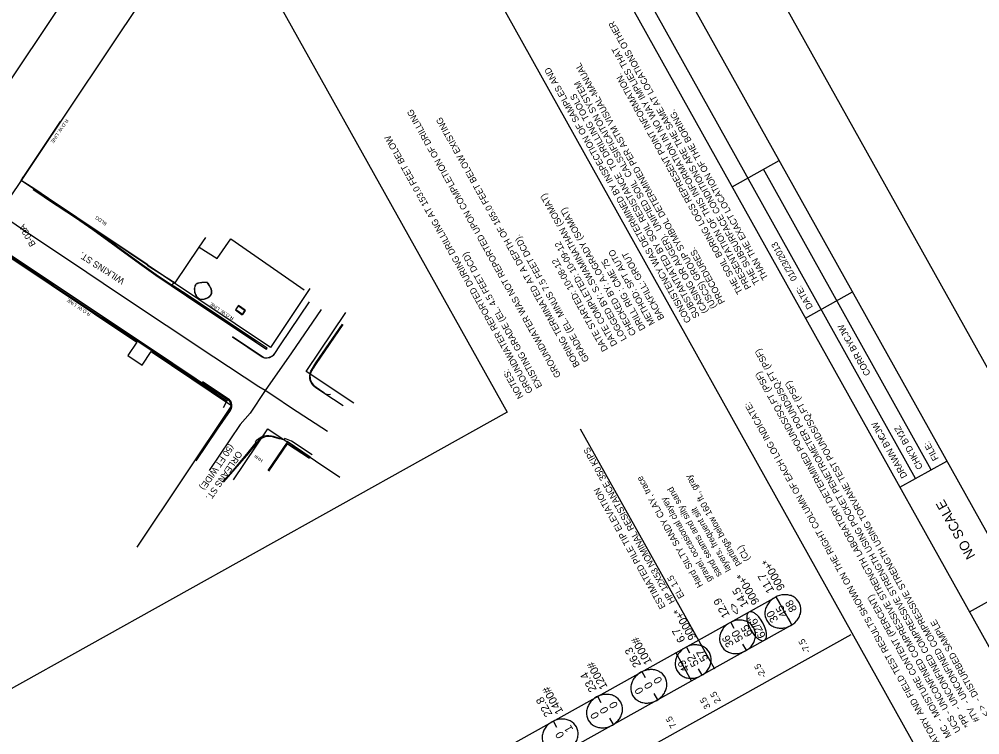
# Model space of a CAD drawing. Extents: x 13482447 to 13495412, y 324533 to 340229.
# Drawn here: x 13494341 to 13495055, y 332109 to 332641 of the extents above; entities that cross this region are included whole.
import ezdxf

# ---------------------------------------------------------------- set-up
doc = ezdxf.new("R2010")
doc.units = 0
for name, color, linetype in [('BORDER', 7, 'Continuous'), ('Default', 7, 'Continuous'), ('DETAIL_TEXT_DIMEN_PR', 7, 'Continuous'), ('Level 1', 7, 'Continuous'), ('TYPICAL_TEXT_DIMEN_PR', 7, 'Continuous'), ('V-ANNO-TEXT', 7, 'Continuous'), ('V-BLDG-IDEN', 7, 'Continuous'), ('V-BLDG-OTLN', 7, 'Continuous'), ('V-PROP-RWAY', 7, 'Continuous'), ('V-PROP-RWAY-IDEN', 7, 'Continuous'), ('V-PVMT-BACK', 7, 'Continuous'), ('V-PVMT-CNTR', 7, 'Continuous'), ('V-PVMT-ROAD', 7, 'Continuous'), ('V-SITE-FENC-DEMO', 7, 'Continuous'), ('V-STRC-WALL', 7, 'Continuous'), ('V-TOPO-IDEN', 7, 'Continuous')]:
    doc.layers.add(name, color=color, linetype=linetype)

# ---------------------------------------------------------------- blocks, each defined once
blk = doc.blocks.new('DGRFC_BLOW$COUNT$ELLIPSE')
at = {"layer": 'Default'}
blk.add_lwpolyline([(0, -0.0274), (0.0061, -0.0265), (0.0089, -0.0254), (0.0104, -0.0246), (0.0118, -0.0238), (0.0132, -0.0228), (0.0145, -0.0218), (0.0157, -0.0206), (0.0168, -0.0194), (0.0179, -0.018), (0.0189, -0.0167), (0.0198, -0.0152), (0.0206, -0.0137), (0.0213, -0.0122), (0.022, -0.0106), (0.023, -0.0071), (0.0236, -0.0036), (0.0238, 0), (0.0236, 0.0036), (0.023, 0.0071), (0.022, 0.0106), (0.0213, 0.0122), (0.0206, 0.0137), (0.0198, 0.0152), (0.0189, 0.0167), (0.0179, 0.018), (0.0168, 0.0194), (0.0157, 0.0206), (0.0145, 0.0218), (0.0132, 0.0228), (0.0118, 0.0238), (0.0104, 0.0246), (0.0089, 0.0254), (0.0061, 0.0265), (0, 0.0274), (-0.0061, 0.0265), (-0.0089, 0.0254), (-0.0104, 0.0246), (-0.0118, 0.0238), (-0.0132, 0.0228), (-0.0145, 0.0218), (-0.0157, 0.0206), (-0.0168, 0.0194), (-0.0179, 0.018), (-0.0189, 0.0167), (-0.0198, 0.0152), (-0.0206, 0.0137), (-0.0213, 0.0122), (-0.022, 0.0106), (-0.023, 0.0071), (-0.0236, 0.0036), (-0.0238, 0), (-0.0236, -0.0036), (-0.023, -0.0071), (-0.022, -0.0106), (-0.0213, -0.0122), (-0.0206, -0.0137), (-0.0198, -0.0152), (-0.0189, -0.0167), (-0.0179, -0.018), (-0.0168, -0.0194), (-0.0157, -0.0206), (-0.0145, -0.0218), (-0.0132, -0.0228), (-0.0118, -0.0238), (-0.0104, -0.0246), (-0.0089, -0.0254), (-0.0061, -0.0265), (0, -0.0274)], dxfattribs=at)

msp = doc.modelspace()

# ---------------------------------------------------------------- linework, layer by layer
at = {"layer": 'Default'}
for points in [[(13494457.44, 332789.11), (13494703.36, 332348.37)], [(13494703.36, 332348.37), (13494205.48, 332070.8)], [(13494374.94, 331916.13), (13494903.54, 332211.14)], [(13494915.18, 332190.27), (13494903.49, 332211.23)], [(13494386.58, 331895.26), (13494915.18, 332190.27)], [(13494959.11, 332182.88), (13494336.71, 331835.6)], [(13494840.6, 332148.67), (13494828.91, 332169.62)]]:
    msp.add_lwpolyline(points, dxfattribs=at)
at = {"layer": 'Level 1'}
for p, q in [((13495412.28, 331751.04), (13494712.57, 333005.04)), ((13495330.65, 331774.2), (13494689.41, 332923.41)), ((13495295.72, 331754.71), (13494654.48, 332903.92)), ((13495223.39, 331712.33), (13494580.84, 332863.9)), ((13495007.21, 332299.13), (13494695.36, 332858.02)), ((13494870.84, 332516.2), (13494905.78, 332535.69)), ((13495018.85, 332305.63), (13494894.11, 332529.18)), ((13494925.4, 332418.38), (13494960.33, 332437.87)), ((13494995.56, 332292.64), (13495030.5, 332312.13)), ((13495047.21, 332200.07), (13495082.14, 332219.56))]:
    msp.add_line(p, q, dxfattribs=at)
at = {"layer": 'TYPICAL_TEXT_DIMEN_PR'}
for p, q in [((13494857.81, 332157.23), (13494758.09, 332335.95)), ((13494906.13, 332206.49), (13494903.54, 332211.14)), ((13494872.38, 332187.6), (13494869.78, 332192.24)), ((13494915.18, 332190.27), (13494912.59, 332194.92)), ((13494839.39, 332169.19), (13494836.8, 332173.84)), ((13494881.43, 332171.38), (13494878.84, 332176.02)), ((13494806.4, 332150.78), (13494803.81, 332155.43)), ((13494848.44, 332152.97), (13494845.85, 332157.61)), ((13494815.45, 332134.56), (13494812.86, 332139.21)), ((13494773.41, 332132.38), (13494770.82, 332137.02)), ((13494740.42, 332113.97), (13494737.83, 332118.61)), ((13494782.46, 332116.15), (13494779.87, 332120.8))]:
    msp.add_line(p, q, dxfattribs=at)
at = {"layer": 'V-BLDG-OTLN'}
for points in [[(13494343.43, 332523.28), (13494342, 332521.11), (13494351.5, 332514.97), (13494362.36, 332507.58), (13494383.44, 332493.51), (13494396.16, 332484.98), (13494436.22, 332458.43), (13494435.76, 332457.89), (13494456.71, 332444.65), (13494474.49, 332471.19), (13494479.39, 332478.39)], [(13494556.95, 332314.92), (13494539.87, 332326.2), (13494525.55, 332304.99)], [(13494526.15, 332304.58), (13494540.09, 332324.93), (13494556.46, 332314.19)]]:
    msp.add_lwpolyline(points, dxfattribs=at)
at = {"layer": 'V-PROP-RWAY'}
for p, q in [((13494162.94, 332339.78), (13494415.51, 332716.95)), ((13494441.77, 332669.89), (13494189.2, 332292.72)), ((13494341.99, 332520.8), (13494371.36, 332564.67)), ((13494527.47, 332396.63), (13494341.99, 332520.8)), ((13494333.01, 332464.24), (13494428.07, 332400.6)), ((13494556.84, 332440.51), (13494527.47, 332396.63)), ((13494554.06, 332378.83), (13494583.43, 332422.71)), ((13494428.07, 332400.6), (13494421.4, 332390.63)), ((13494421.4, 332390.63), (13494432.03, 332383.51)), ((13494432.03, 332383.51), (13494438.71, 332393.48)), ((13494438.71, 332393.48), (13494498.54, 332353.42)), ((13494589.54, 332355.08), (13494554.06, 332378.83)), ((13494498.54, 332353.42), (13494428.05, 332248.13)), ((13494500.08, 332298.2), (13494525.4, 332336.02)), ((13494525.4, 332336.02), (13494578.99, 332300.15))]:
    msp.add_line(p, q, dxfattribs=at)
at = {"layer": 'V-PVMT-BACK'}
for points in [[(13494581.22, 332413.73), (13494561.51, 332384.74), (13494559.24, 332381.12), (13494558.02, 332379), (13494557.55, 332377.99), (13494557.06, 332376.48), (13494556.86, 332374.95), (13494556.88, 332374.17), (13494557.05, 332373.11), (13494557.25, 332372.4), (13494557.8, 332371.05), (13494558.08, 332370.52), (13494558.75, 332369.53), (13494559.54, 332368.63), (13494560.13, 332368.07), (13494561.49, 332367.02), (13494567.19, 332363.04), (13494567.06, 332362.79)], [(13494472.22, 332312.25), (13494487.68, 332336.18), (13494491.11, 332341.45), (13494496.52, 332348.72), (13494497.47, 332350.12), (13494498.04, 332351.33), (13494498.31, 332352.64), (13494498.27, 332353.98), (13494497.9, 332355.27), (13494497.25, 332356.44), (13494496.34, 332357.41), (13494495.77, 332357.83)], [(13494492.65, 332351.94), (13494494.95, 332356.59), (13494495.77, 332357.83)], [(13494534.6, 332328.53), (13494533.98, 332328.69), (13494529.82, 332329.93), (13494529.1, 332330.12), (13494527.22, 332330.42), (13494525.32, 332330.39), (13494523.45, 332330.05), (13494521.67, 332329.4), (13494520.02, 332328.46), (13494518.55, 332327.25), (13494517.3, 332325.82), (13494517.24, 332325.73), (13494511.17, 332318.01), (13494492.55, 332296.67)]]:
    msp.add_lwpolyline(points, dxfattribs=at)
at = {"layer": 'V-PVMT-CNTR'}
for points in [[(13494569.9, 332334.19), (13494543.09, 332351.45), (13494530, 332360.31), (13494523.55, 332364.49), (13494518.82, 332367.3), (13494485.34, 332389.34), (13494450.03, 332412.95), (13494414.45, 332436.54), (13494379.49, 332460.03), (13494345.6, 332482.5), (13494327.31, 332495.27), (13494298.14, 332514.29), (13494271.57, 332532.13), (13494238.98, 332554.15), (13494204.65, 332577.08), (13494171.55, 332599.53), (13494143.69, 332618.17)], [(13494565.21, 332424.85), (13494543.23, 332392.53), (13494523.55, 332364.49), (13494512.34, 332347.83), (13494505.02, 332339.39), (13494481.96, 332305.2)]]:
    msp.add_lwpolyline(points, dxfattribs=at)
at = {"layer": 'V-PVMT-ROAD'}
for points in [[(13494383.26, 332493.54), (13494382.64, 332493.41), (13494362.55, 332506.72), (13494362.46, 332507.55)], [(13494474.49, 332471.19), (13494487.87, 332462.68), (13494497.88, 332477.35), (13494527.28, 332457.02), (13494552.61, 332439.58)], [(13494480.72, 332444.84), (13494477.81, 332444.91), (13494476.54, 332444.88), (13494474.88, 332444.71), (13494473.49, 332444.36), (13494472.9, 332444.11), (13494472.24, 332443.68), (13494471.95, 332443.42), (13494471.58, 332442.97), (13494471.16, 332442.16), (13494470.86, 332440.82), (13494470.82, 332440.16), (13494470.89, 332438.75), (13494471.09, 332437.67), (13494471.6, 332436.08), (13494471.95, 332435.34), (13494472.52, 332434.43), (13494472.85, 332434.02), (13494473.39, 332433.48), (13494474.32, 332432.86), (13494475.31, 332432.51), (13494476.02, 332432.4), (13494477.5, 332432.44), (13494478.25, 332432.58), (13494479.73, 332433.05), (13494480.66, 332433.5), (13494481.78, 332434.21), (13494482.27, 332434.61), (13494483.15, 332435.58), (13494483.59, 332436.35), (13494483.77, 332436.88), (13494483.89, 332438.01), (13494483.83, 332438.61), (13494483.51, 332439.89), (13494482.93, 332441.29), (13494482.42, 332442.3), (13494481.12, 332444.54)], [(13494480.58, 332444.78), (13494477.75, 332444.82), (13494476.51, 332444.77), (13494474.89, 332444.6), (13494473.54, 332444.25), (13494472.97, 332444), (13494472.32, 332443.58), (13494472.04, 332443.33), (13494471.68, 332442.89), (13494471.28, 332442.1), (13494470.99, 332440.76), (13494470.95, 332440.09), (13494471.05, 332438.68), (13494471.26, 332437.59), (13494471.8, 332436.01), (13494472.17, 332435.27), (13494472.75, 332434.37), (13494473.09, 332433.97), (13494473.64, 332433.44), (13494474.58, 332432.85), (13494475.54, 332432.54), (13494476.22, 332432.46), (13494477.64, 332432.54), (13494478.36, 332432.69), (13494479.77, 332433.18), (13494480.65, 332433.62), (13494481.72, 332434.33), (13494482.18, 332434.73), (13494483.03, 332435.67), (13494483.46, 332436.46), (13494483.64, 332437), (13494483.74, 332438.15), (13494483.66, 332438.76), (13494483.3, 332440.05), (13494482.65, 332441.46), (13494482.08, 332442.48), (13494480.65, 332444.73)], [(13494556.28, 332430.52), (13494534.75, 332398.59), (13494530.07, 332391.41), (13494529.47, 332390.66), (13494529.02, 332390.24), (13494527.99, 332389.55), (13494526.72, 332388.98), (13494526.05, 332388.77), (13494525.02, 332388.59), (13494523.93, 332388.57), (13494523.39, 332388.64), (13494522.58, 332388.85), (13494521.41, 332389.44), (13494499.21, 332404.28)], [(13494508.68, 332424.44), (13494503.76, 332427.86), (13494501.51, 332424.52), (13494506.52, 332420.94), (13494508.68, 332424.44)], [(13494506.67, 332421.21), (13494501.76, 332424.6), (13494503.75, 332427.6), (13494508.73, 332424.22), (13494506.67, 332421.21)], [(13494581.44, 332353.13), (13494567.08, 332362.54), (13494561.17, 332366.67), (13494559.77, 332367.73), (13494558.59, 332369.03), (13494557.66, 332370.52), (13494557.01, 332372.15), (13494556.67, 332373.88), (13494556.65, 332375.63), (13494556.94, 332377.36), (13494557.55, 332379.01), (13494557.88, 332379.66), (13494561.17, 332385.16), (13494580.94, 332413.83)], [(13494529.95, 332391.58), (13494529.12, 332390.63), (13494528.66, 332390.22), (13494527.9, 332389.71), (13494526.94, 332389.27), (13494526.44, 332389.09), (13494525.71, 332388.89), (13494524.82, 332388.72), (13494524.47, 332388.7), (13494523.75, 332388.72), (13494522.76, 332388.94), (13494522.25, 332389.13), (13494521.5, 332389.55), (13494499.3, 332404.4)], [(13494472.3, 332312.21), (13494488.13, 332335.88), (13494497.78, 332349.83), (13494498.41, 332351.09), (13494498.75, 332352.46), (13494498.78, 332353.88), (13494498.48, 332355.26), (13494497.89, 332356.54), (13494497.02, 332357.65), (13494496, 332358.49), (13494477.01, 332371.04)], [(13494495.44, 332358.14), (13494476.75, 332370.64)], [(13494495.44, 332358.14), (13494495.28, 332358.46), (13494476.92, 332370.9)], [(13494567.06, 332362.79), (13494568.35, 332362.13), (13494569.75, 332361.78), (13494571.2, 332361.73), (13494572.19, 332361.89)], [(13494492.1, 332296.91), (13494499.81, 332305.04), (13494510.87, 332318.46), (13494516.88, 332326.01), (13494516.31, 332326.42), (13494517.57, 332327.89), (13494519.05, 332329.12), (13494520.72, 332330.1), (13494522.53, 332330.78), (13494524.42, 332331.16), (13494526.35, 332331.22), (13494528.27, 332330.97), (13494529.56, 332330.61), (13494534.73, 332328.98)], [(13494558.52, 332316.63), (13494543.11, 332327.03), (13494538.17, 332328.88), (13494537.37, 332327.87), (13494534.6, 332328.53)], [(13494557, 332315.02), (13494539.78, 332326.54)]]:
    msp.add_lwpolyline(points, dxfattribs=at)
at = {"layer": 'V-SITE-FENC-DEMO'}
msp.add_lwpolyline([(13494516.88, 332400.98), (13494454.22, 332442.65), (13494455.75, 332444.95)], dxfattribs=at)
at = {"layer": 'V-STRC-WALL'}
for points in [[(13494351.43, 332514.71), (13494351.07, 332514.18), (13494355.23, 332511.27), (13494362.38, 332506.51), (13494382.49, 332493.21), (13494395.33, 332484.24), (13494430.14, 332459.16), (13494442.14, 332450.44), (13494465.06, 332435.12), (13494500.32, 332411.42), (13494524.53, 332395.31), (13494524.9, 332396.06), (13494465.42, 332435.8), (13494455.18, 332442.46)], [(13494351.43, 332514.71), (13494355.67, 332511.89), (13494362.4, 332507.39), (13494362.49, 332506.66), (13494382.59, 332493.35), (13494383.18, 332493.48), (13494395.72, 332484.73), (13494430.44, 332459.61), (13494442.51, 332450.97), (13494455.18, 332442.46)], [(13494494.85, 332356.7), (13494495.33, 332357.66), (13494472.3, 332373.02), (13494438.14, 332395.84), (13494402.73, 332419.43), (13494366.86, 332443.47), (13494332.26, 332466.53), (13494315.83, 332477.56), (13494315.57, 332477.73)], [(13494494.85, 332356.7), (13494471.69, 332372.25), (13494437.65, 332394.97), (13494402.11, 332418.69), (13494366.37, 332442.49), (13494331.57, 332465.72), (13494317.33, 332475.26)]]:
    msp.add_lwpolyline(points, dxfattribs=at)

# ---------------------------------------------------------------- block references
at = {"layer": 'Default'}
for p, xscale, yscale, rotation in [((13494908.57, 332200.26), 503.9370078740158, 503.93700787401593, 119.16052892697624), ((13494908.57, 332200.26), 503.9370078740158, 503.93700787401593, 119.16052892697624), ((13494888.99, 332189.28), 503.9370078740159, 189.3040511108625, 119.16052892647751), ((13494874.82, 332181.37), 503.9370078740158, 503.93700787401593, 119.16052892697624), ((13494874.82, 332181.37), 503.9370078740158, 503.93700787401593, 119.16052892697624), ((13494841.83, 332162.96), 503.9370078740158, 503.93700787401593, 119.16052892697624), ((13494841.83, 332162.96), 503.9370078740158, 503.93700787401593, 119.16052892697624), ((13494808.84, 332144.56), 503.9370078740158, 503.93700787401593, 119.16052892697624), ((13494808.84, 332144.56), 503.9370078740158, 503.93700787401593, 119.16052892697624), ((13494775.85, 332126.15), 503.9370078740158, 503.93700787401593, 119.16052892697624), ((13494775.85, 332126.15), 503.9370078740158, 503.93700787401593, 119.16052892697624), ((13494742.86, 332107.74), 503.9370078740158, 503.93700787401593, 119.16052892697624), ((13494742.86, 332107.74), 503.9370078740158, 503.93700787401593, 119.16052892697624)]:
    msp.add_blockref('DGRFC_BLOW$COUNT$ELLIPSE', p, dxfattribs=dict(at, xscale=xscale, yscale=yscale, rotation=rotation))

# ---------------------------------------------------------------- texts
at = {"layer": 'BORDER'}
for s, p in [('THE SUBSURFACE CONDITIONS ARE THE SAME AT LOCATIONS OTHER ', (13494891.49, 332444.89)), ('PRESENTATION OF THIS INFORMATION IN NO WAY IMPLIES THAT ', (13494885.2, 332441.38)), ('CONSISTENCY WAS DETERMINED BY INSPECTION OF SAMPLES AND ', (13494840.51, 332416.44)), ('(USCS) GROUP SYMBOL DETERMINED PER ASTM VISUAL-MANUAL ', (13494859.37, 332426.97)), ('THE SOIL BORING LOGS REPRESENT POINT INFORMATION. ', (13494878.91, 332437.88)), ('(CASING OR AUGER).  UNIFIED SOIL  CALSSIFICAITON SYSTEM ', (13494853.08, 332423.46)), ('SUBSTANTIATED BY SOIL RESISTANCE  TO DRILLING TOOLS ', (13494846.79, 332419.95)), ('THAN THE EXACT LOCATION OF THE BORING.', (13494897.78, 332448.4)), ('PROCEDURES.', (13494865.66, 332430.48)), ('*PP  - UNCONFINED COMPRESSIVE STRENGTH USING POCKET PENETROMETER POUNDS/SQ.FT (PSF)', (13495048.01, 332115.56)), ('UCS - UNCONFINED COMPRESSIVE STRENGTH LABORATORY DETERMINED POUNDS/SQ.FT (PSF)', (13495041.03, 332111.67)), ('#TV  - UNCONFINED COMPRESSIVE STRENGTH USING TORVANE TEST POUNDS/SQ.FT (PSF)', (13495055, 332119.46)), ('LABORATORY AND FIELD TEST RESULTS SHOWN ON THE RIGHT COLUMN OF EACH LOG INDICATE:', (13495035.63, 332084.53)), ('MC  - MOISTURE CONTENT (PERCENT)', (13495034.04, 332107.77)), ('< >  - DISTURBED SAMPLE   ', (13495061.98, 332123.36))]:
    msp.add_text(s, height=4.8, rotation=119.16053, dxfattribs=at).set_placement(p)
at = {"layer": 'Default'}
for s, height, p in [('9000+*', 5.952, (13494910.31, 332217.83)), ('9000+*', 5.952, (13494891.29, 332207.22)), (' 11.7', 5.952, (13494903.32, 332213.93)), (' 11.7', 5.952, (13494903.32, 332213.93)), (' 14.5', 5.952, (13494884.3, 332203.32)), (' 14.5', 5.952, (13494884.3, 332203.32)), (' 12.9', 5.952, (13494870.33, 332195.52)), (' 12.9', 5.952, (13494870.33, 332195.52)), ('<>', 5.952, (13494877.32, 332199.42)), ('<>', 5.952, (13494877.32, 332199.42)), ('45', 5.952, (13494912.28, 332197.88)), ('45', 5.952, (13494912.28, 332197.88)), ('88', 5.952, (13494919.26, 332201.77)), ('88', 5.952, (13494919.26, 332201.77)), ('9000+*', 5.952, (13494844.33, 332181.01)), ('62/6"', 5.952, (13494896.09, 332182.19)), ('30', 5.952, (13494905.29, 332193.98)), ('30', 5.952, (13494905.29, 332193.98)), ('65', 5.952, (13494886.27, 332183.37)), ('65', 5.952, (13494886.27, 332183.37)), ('1000#', 5.952, (13494811.34, 332162.61)), ('1000#', 5.952, (13494811.34, 332162.61)), (' 6.7', 5.952, (13494837.34, 332177.11)), (' 6.7', 5.952, (13494837.34, 332177.11)), ('36', 5.952, (13494872.3, 332175.57)), ('36', 5.952, (13494872.3, 332175.57)), ('50', 5.952, (13494879.29, 332179.47)), ('50', 5.952, (13494879.29, 332179.47)), (' 26.3', 5.952, (13494804.35, 332158.71)), (' 26.3', 5.952, (13494804.35, 332158.71)), ('52', 5.952, (13494846.3, 332161.06)), ('52', 5.952, (13494846.3, 332161.06)), ('57', 5.952, (13494853.28, 332164.96)), ('57', 5.952, (13494853.28, 332164.96)), ('1200#', 5.952, (13494778.35, 332144.2)), ('1200#', 5.952, (13494778.35, 332144.2)), ('49', 5.952, (13494839.31, 332157.16)), ('49', 5.952, (13494839.31, 332157.16)), (' 23.4', 5.952, (13494771.36, 332140.3)), (' 23.4', 5.952, (13494771.36, 332140.3)), ('0', 5.95, (13494812.18, 332144.68)), ('0', 5.95, (13494812.18, 332144.68)), ('0', 5.95, (13494819.16, 332148.58)), ('0', 5.95, (13494819.16, 332148.58)), ('1400#', 5.952, (13494745.36, 332125.79)), ('1400#', 5.952, (13494745.36, 332125.79)), ('0', 5.95, (13494805.19, 332140.78)), ('0', 5.95, (13494805.19, 332140.78)), (' 22.8', 5.952, (13494738.37, 332121.89)), (' 22.8', 5.952, (13494738.37, 332121.89)), ('0', 5.95, (13494786.17, 332130.17)), ('0', 5.95, (13494786.17, 332130.17)), ('0', 5.95, (13494772.2, 332122.38)), ('0', 5.95, (13494772.2, 332122.38)), ('0', 5.95, (13494779.19, 332126.27)), ('0', 5.95, (13494779.19, 332126.27)), ('0', 5.95, (13494746.2, 332107.87)), ('0', 5.95, (13494746.2, 332107.87)), ('1', 5.95, (13494752.8, 332112.45)), ('1', 5.95, (13494752.8, 332112.45))]:
    msp.add_text(s, height=height, rotation=119.16053, dxfattribs=at).set_placement(p)
at = {"layer": 'DETAIL_TEXT_DIMEN_PR'}
for s, p in [('GROUNDWATER WAS NOT REPORTED UPON COMPLETION OF DRILLING ', (13494743.7, 332375.67)), ('BORING TERMINATED AT A DEPTH OF 165.0 FEET BELOW EXISTING ', (13494757.67, 332383.46)), ('GROUNDWATER REPORTED DURING DRILLING AT 153.0 FEET BELOW', (13494722.74, 332363.97)), ('LOGGED BY: S.SWAMINATHAN (SOMAT)', (13494792.61, 332402.95)), ('CHECKED BY: A.OGRADY (SOMAT)', (13494799.59, 332406.85)), ('B-03A', (13494353.06, 332473.25)), ('GRADE (EL. MINUS 7.5 FEET DCD).', (13494764.66, 332387.36)), ('DATE COMPLETED: 10-09-12', (13494785.62, 332399.05)), ('EXISTING GRADE (EL. 4.5 FEET DCD)', (13494729.73, 332367.87)), ('METHOD: SPT AUTO', (13494813.56, 332414.65)), ('BACKFILL: GROUT', (13494820.55, 332418.54)), ('DATE STARTED: 10-08-12', (13494778.63, 332395.16)), ('DRILL RIG : CME 75', (13494806.58, 332410.75)), ('NOTES:', (13494715.76, 332360.07)), ('HP 12X53 NOMINAL RESISTANCE 350 KIPS', (13494828.45, 332207.61)), ('Hard SILTY SANDY CLAY, trace ', (13494849.3, 332219.58)), ('partings below 160 ft., gray ', (13494877.24, 332235.17)), ('ESTIMATED PILE TIP ELEVATION', (13494821.47, 332203.72)), ('sand seams and silty sand ', (13494863.27, 332227.38)), ('gravel, occasional clayey ', (13494856.28, 332223.48)), ('layers, frequent silt ', (13494870.26, 332231.28)), ('(CL)', (13494884.23, 332239.07)), ('EL 1.5', (13494835.44, 332211.51)), ('-7.5', (13494929.38, 332170.76)), ('-2.5', (13494896.39, 332152.36)), ('2.5', (13494862.63, 332133.46)), ('3.5', (13494854.94, 332129.17)), ('7.5', (13494829.64, 332115.05))]:
    msp.add_text(s, height=4.8, rotation=119.16053, dxfattribs=at).set_placement(p)
at = {"layer": 'Level 1'}
for s, height, p in [('01/23/2013', 4.8, (13494919.33, 332447.58)), ('DATE:', 4.8, (13494931, 332426.67)), ('CJW               ', 4.8, (13494959.91, 332402.25)), ('CORR BY:', 4.8, (13494973.92, 332377.15)), ('CJW                                 ', 4.8, (13494985.09, 332329.76)), ('JZ                            ', 4.8, (13494998.73, 332332.68)), ('DRAWN BY:', 4.8, (13495001.18, 332300.93)), ("CHK'D BY:", 4.8, (13495012.82, 332307.43)), ('FILE:', 4.8, (13495024.46, 332313.92)), ('NO SCALE', 7.2, (13495051.89, 332241.6))]:
    msp.add_text(s, height=height, rotation=119.16053, dxfattribs=at).set_placement(p)
at = {"layer": 'V-ANNO-TEXT'}
for s, rotation, p in [('WILKINS ST.', 147.22098, (13494419.47, 332447.2)), ('(50 FT WIDE)', 235.78017, (13494496.84, 332325.28)), ('ORLEANS ST.', 235.78017, (13494502.98, 332320.08))]:
    msp.add_text(s, height=4.8, rotation=rotation, dxfattribs=at).set_placement(p)
at = {"layer": 'V-BLDG-IDEN'}
msp.add_text('BLDG', height=2.56, rotation=145.04331, dxfattribs=at).set_placement((13494406.03, 332489.18))
at = {"layer": 'V-PROP-RWAY-IDEN'}
for rotation, p in [(236.28918, (13494375.27, 332566.74)), (146.19962, (13494394.04, 332421.84)), (146.19962, (13494500.49, 332418.84))]:
    msp.add_text('R.O.W. LINE', height=2.56, rotation=rotation, dxfattribs=at).set_placement(p)
at = {"layer": 'V-TOPO-IDEN'}
msp.add_text('HH#', height=2.56, rotation=145.04331, dxfattribs=at).set_placement((13494522.2, 332313.08))

doc.saveas('drawing.dxf')
